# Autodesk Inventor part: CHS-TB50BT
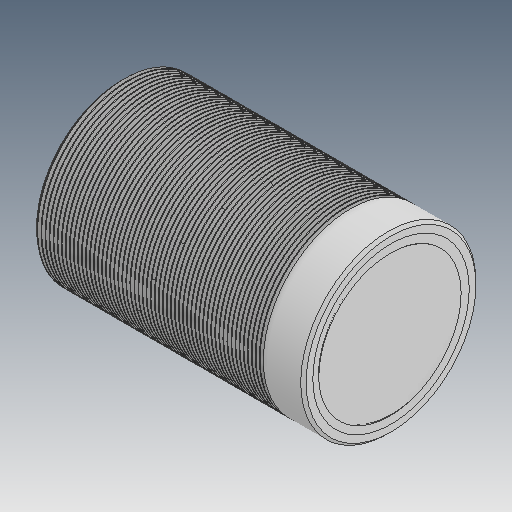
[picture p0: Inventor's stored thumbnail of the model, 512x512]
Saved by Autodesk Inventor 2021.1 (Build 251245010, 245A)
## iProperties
Created: 2019-04
Part Number: CHS-TB50BT
Material: Ogólny
Document SubType Name: Modeling
Designer: user
Density: 1 g/cm^3
Appearance: Domyślna
Author: user
Revision Number: ÈÎºÎ
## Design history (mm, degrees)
feature "ÊäÈë1"
feature "ÊäÈë2"
node "Bryła1"
node "Bryła2"
